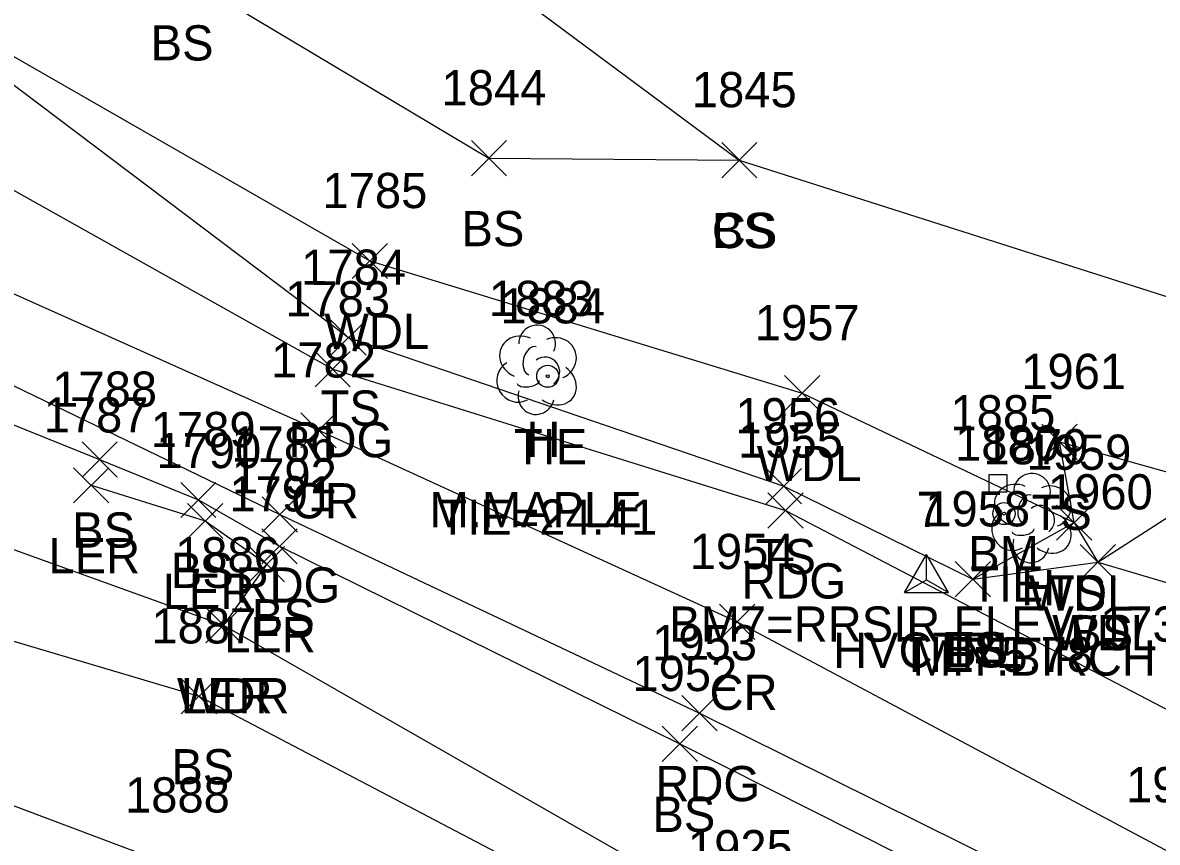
# Model space of a CAD drawing. Extents: x 1512665 to 1513714, y 110636 to 112816.
# Drawn here: x 1512769.8 to 1512834.1, y 110869.1 to 110915.7 of the extents above; entities that cross this region are included whole.
import ezdxf

# ---------------------------------------------------------------- set-up
doc = ezdxf.new("R2010")
doc.units = 0
for name, color, linetype in [('C_A', 7, 'Continuous'), ('C_C', 7, 'Continuous'), ('C_I', 7, 'Continuous'), ('CBP', 7, 'Continuous'), ('CPBM', 7, 'Continuous'), ('CPSM', 7, 'Continuous'), ('L_A', 7, 'Continuous'), ('L_C', 7, 'Continuous'), ('L_I', 7, 'Continuous'), ('L_TIC', 7, 'Continuous'), ('LARO', 7, 'Continuous'), ('LAWA', 7, 'Continuous'), ('LELB', 7, 'Continuous'), ('LTD', 7, 'Continuous'), ('P_A', 7, 'Continuous'), ('P_I', 7, 'Continuous'), ('P_TIC', 7, 'Continuous'), ('PEU', 7, 'Continuous'), ('PRC', 7, 'Continuous')]:
    doc.layers.add(name, color=color, linetype=linetype)

msp = doc.modelspace()

# ---------------------------------------------------------------- linework, layer by layer
at = {"layer": 'CBP'}
for centre, radius in [((1512799.556, 110895.606), 0.625), ((1512799.556, 110895.606), 0.0833), ((1512825.449, 110887.809), 0.625), ((1512825.449, 110887.809), 0.0833)]:
    msp.add_circle(centre, radius, dxfattribs=at)
at = {"layer": 'CPBM'}
for p, q in [((1512824.602, 110889.032), (1512824.602, 110890.032)), ((1512824.602, 110890.032), (1512825.602, 110890.032)), ((1512825.602, 110890.032), (1512825.602, 110889.032)), ((1512825.104, 110889.533), (1512825.104, 110889.533)), ((1512825.104, 110889.533), (1512825.104, 110889.533)), ((1512825.602, 110889.032), (1512824.602, 110889.032))]:
    msp.add_line(p, q, dxfattribs=at)
at = {"layer": 'CPSM'}
for p, q in [((1512819.805, 110883.327), (1512821.055, 110885.492)), ((1512819.805, 110883.327), (1512821.055, 110885.492)), ((1512819.805, 110883.327), (1512821.055, 110885.492)), ((1512819.805, 110883.327), (1512821.055, 110885.492)), ((1512819.805, 110883.327), (1512821.055, 110885.492)), ((1512819.805, 110883.327), (1512821.055, 110885.492)), ((1512819.805, 110883.327), (1512821.055, 110885.492)), ((1512822.305, 110883.327), (1512821.055, 110885.492)), ((1512821.055, 110884.048), (1512821.055, 110885.492)), ((1512822.305, 110883.327), (1512821.055, 110885.492)), ((1512821.055, 110884.048), (1512821.055, 110885.492)), ((1512822.305, 110883.327), (1512821.055, 110885.492)), ((1512821.055, 110884.048), (1512821.055, 110885.492)), ((1512822.305, 110883.327), (1512821.055, 110885.492)), ((1512821.055, 110884.048), (1512821.055, 110885.492)), ((1512822.305, 110883.327), (1512821.055, 110885.492)), ((1512821.055, 110884.048), (1512821.055, 110885.492)), ((1512822.305, 110883.327), (1512821.055, 110885.492)), ((1512821.055, 110884.048), (1512821.055, 110885.492)), ((1512822.305, 110883.327), (1512821.055, 110885.492)), ((1512821.055, 110884.048), (1512821.055, 110885.492)), ((1512819.805, 110883.327), (1512821.055, 110884.048)), ((1512819.805, 110883.327), (1512821.055, 110884.048)), ((1512819.805, 110883.327), (1512821.055, 110884.048)), ((1512819.805, 110883.327), (1512821.055, 110884.048)), ((1512819.805, 110883.327), (1512821.055, 110884.048)), ((1512819.805, 110883.327), (1512821.055, 110884.048)), ((1512819.805, 110883.327), (1512821.055, 110884.048)), ((1512821.055, 110884.048), (1512821.055, 110884.048)), ((1512821.055, 110884.048), (1512822.305, 110883.327)), ((1512821.055, 110884.048), (1512821.055, 110884.048)), ((1512821.055, 110884.048), (1512822.305, 110883.327)), ((1512821.055, 110884.048), (1512821.055, 110884.048)), ((1512821.055, 110884.048), (1512822.305, 110883.327)), ((1512821.055, 110884.048), (1512821.055, 110884.048)), ((1512821.055, 110884.048), (1512822.305, 110883.327)), ((1512821.055, 110884.048), (1512821.055, 110884.048)), ((1512821.055, 110884.048), (1512822.305, 110883.327)), ((1512821.055, 110884.048), (1512821.055, 110884.048)), ((1512821.055, 110884.048), (1512822.305, 110883.327)), ((1512821.055, 110884.048), (1512821.055, 110884.048)), ((1512821.055, 110884.048), (1512822.305, 110883.327)), ((1512819.805, 110883.327), (1512822.305, 110883.327)), ((1512819.805, 110883.327), (1512822.305, 110883.327)), ((1512819.805, 110883.327), (1512822.305, 110883.327)), ((1512819.805, 110883.327), (1512822.305, 110883.327)), ((1512819.805, 110883.327), (1512822.305, 110883.327)), ((1512819.805, 110883.327), (1512822.305, 110883.327)), ((1512819.805, 110883.327), (1512822.305, 110883.327))]:
    msp.add_line(p, q, dxfattribs=at)
at = {"layer": 'L_TIC'}
for points in [[(1512795.221, 110906.99), (1512797.221, 110908.99)], [(1512797.221, 110906.99), (1512795.221, 110908.99)], [(1512809.428, 110906.882), (1512811.428, 110908.882)], [(1512811.428, 110906.882), (1512809.428, 110908.882)], [(1512809.428, 110906.882), (1512811.428, 110908.882)], [(1512811.428, 110906.882), (1512809.428, 110908.882)], [(1512788.467, 110901.153), (1512790.467, 110903.153)], [(1512790.467, 110901.153), (1512788.467, 110903.153)], [(1512787.256, 110896.799), (1512789.256, 110898.799)], [(1512789.256, 110896.799), (1512787.256, 110898.799)], [(1512812.998, 110893.649), (1512814.998, 110895.649)], [(1512814.998, 110893.649), (1512812.998, 110895.649)], [(1512827.602, 110890.881), (1512829.602, 110892.881)], [(1512829.602, 110890.881), (1512827.602, 110892.881)], [(1512773.129, 110889.874), (1512775.129, 110891.874)], [(1512775.129, 110889.874), (1512773.129, 110891.874)], [(1512772.643, 110888.412), (1512774.643, 110890.412)], [(1512774.643, 110888.412), (1512772.643, 110890.412)], [(1512811.95, 110888.365), (1512813.95, 110890.365)], [(1512813.95, 110888.365), (1512811.95, 110890.365)], [(1512778.73, 110887.581), (1512780.73, 110889.581)], [(1512780.73, 110887.581), (1512778.73, 110889.581)], [(1512779.123, 110886.389), (1512781.123, 110888.389)], [(1512781.123, 110886.389), (1512779.123, 110888.389)], [(1512828.426, 110886.292), (1512830.426, 110888.292)], [(1512830.426, 110886.292), (1512828.426, 110888.292)], [(1512828.426, 110886.292), (1512830.426, 110888.292)], [(1512830.426, 110886.292), (1512828.426, 110888.292)], [(1512783.329, 110884.95), (1512785.329, 110886.95)], [(1512785.329, 110884.95), (1512783.329, 110886.95)], [(1512829.768, 110884.044), (1512831.768, 110886.044)], [(1512831.768, 110884.044), (1512829.768, 110886.044)], [(1512829.768, 110884.044), (1512831.768, 110886.044)], [(1512831.768, 110884.044), (1512829.768, 110886.044)], [(1512782.613, 110883.931), (1512784.613, 110885.931)], [(1512784.613, 110883.931), (1512782.613, 110885.931)], [(1512822.675, 110883.08), (1512824.675, 110885.08)], [(1512824.675, 110883.08), (1512822.675, 110885.08)], [(1512822.675, 110883.08), (1512824.675, 110885.08)], [(1512824.675, 110883.08), (1512822.675, 110885.08)], [(1512780.153, 110880.469), (1512782.153, 110882.469)], [(1512782.153, 110880.469), (1512780.153, 110882.469)], [(1512780.153, 110880.469), (1512782.153, 110882.469)], [(1512782.153, 110880.469), (1512780.153, 110882.469)], [(1512778.757, 110876.432), (1512780.757, 110878.432)], [(1512780.757, 110876.432), (1512778.757, 110878.432)], [(1512806.054, 110873.728), (1512808.054, 110875.728)], [(1512808.054, 110873.728), (1512806.054, 110875.728)]]:
    msp.add_lwpolyline(points, dxfattribs=at)
at = {"layer": 'LARO'}
msp.add_lwpolyline([(1512773.643, 110889.412), (1512780.123, 110887.389), (1512783.613, 110884.931), (1512781.153, 110881.469)], dxfattribs=at)
at = {"layer": 'LAWA'}
for points in [[(1512760.327, 110918.9), (1512789.467, 110902.153), (1512813.998, 110894.649), (1512829.426, 110887.292), (1512830.768, 110885.044), (1512838.882, 110882.648), (1512840.963, 110881.395), (1512843.663, 110878.579), (1512861.274, 110870.427), (1512887.257, 110856.133), (1512901.813, 110849.485), (1512918.081, 110842.567)], [(1512680.491, 110906.601), (1512690.439, 110907.088), (1512704.388, 110894.866), (1512725.937, 110900.333), (1512738.133, 110894.414), (1512761.21, 110888.671), (1512781.153, 110881.469), (1512810.207, 110864.835), (1512817.695, 110861.883), (1512832.481, 110853.078), (1512847.518, 110845.492), (1512864.918, 110836.029), (1512870.718, 110832.572), (1512881.895, 110825.79), (1512904.855, 110814.165), (1512921.132, 110807.474)]]:
    msp.add_lwpolyline(points, dxfattribs=at)
at = {"layer": 'LELB'}
for points in [[(1512721.894, 110948.789), (1512722.497, 110942.68), (1512730.744, 110933.358), (1512741.905, 110924.629), (1512760.327, 110918.9), (1512788.256, 110897.799), (1512812.95, 110889.365), (1512823.675, 110884.08), (1512829.426, 110887.292), (1512828.602, 110891.881), (1512837.516, 110889.389), (1512842.176, 110886.401), (1512840.963, 110881.395), (1512842.492, 110877.537), (1512859.927, 110867.233), (1512885.327, 110852.839), (1512900.342, 110845.897), (1512916.833, 110839.511), (1512931.348, 110831.636), (1512947.325, 110821.384)], [(1512700.679, 110948.394), (1512702.883, 110937.76), (1512707.699, 110928.255), (1512715.725, 110919.825), (1512729.364, 110912.396), (1512733.114, 110910.816), (1512749.564, 110901.484), (1512765.39, 110894.395), (1512774.129, 110890.874), (1512779.73, 110888.581), (1512784.329, 110885.95), (1512807.054, 110874.728), (1512832.029, 110862.151), (1512849.873, 110852.9), (1512877.541, 110837.789), (1512892.067, 110830.383), (1512907.918, 110822.224), (1512921.56, 110815.361), (1512936.611, 110807.627), (1512945.797, 110795.178), (1512949.896, 110789.739), (1512950.992, 110781.568)], [(1512775.007, 110936.434), (1512793.008, 110920.829), (1512810.428, 110907.882)], [(1512772.715, 110925.351), (1512778.581, 110918.536), (1512796.221, 110907.99), (1512810.428, 110907.882), (1512837.589, 110899.205), (1512847.527, 110891.123)], [(1512685.371, 110901.62), (1512704.388, 110894.866), (1512721.833, 110890.384), (1512736.947, 110883.291), (1512758.15, 110875.388), (1512778.26, 110867.834), (1512805.478, 110853.5), (1512829.241, 110847.859), (1512845.122, 110839.118), (1512864.918, 110836.029)], [(1512738.133, 110894.414), (1512760.682, 110883.092), (1512779.757, 110877.432), (1512809.283, 110861.943), (1512816.233, 110858.697), (1512830.12, 110852.432), (1512847.518, 110845.492)], [(1512823.675, 110884.08), (1512830.768, 110885.044), (1512837.516, 110889.389)]]:
    msp.add_lwpolyline(points, dxfattribs=at)
at = {"layer": 'LTD'}
for p, q in [((1512798.908, 110896.026), (1512798.908, 110896.026)), ((1512798.908, 110896.026), (1512798.908, 110896.026)), ((1512826.988, 110887.604), (1512826.988, 110887.604)), ((1512826.988, 110887.604), (1512826.988, 110887.604))]:
    msp.add_line(p, q, dxfattribs=at)
for centre in [(1512798.955, 110897.46), (1512827.035, 110889.038)]:
    msp.add_arc(centre, 1.047, 335.52715, 180.95627, dxfattribs=at)
for centre, major_axis, ratio, start_param, end_param in [((1512798.116, 110896.693), (1.21, -0.512), 0.895232, 1.570796, 4.712389), ((1512799.95, 110896.61), (-1.141, -0.483), 0.949671, 1.570796, 4.712389), ((1512798.7, 110896.485), (-0.208, -0.792), 0.645439, 3.141593, 6.283185), ((1512797.825, 110895.318), (0.584, -1.042), 0.959034, 3.141593, 6.283185), ((1512799.408, 110895.86), (-0.5, 0.667), 0.989748, 3.141593, 6.283185), ((1512799.908, 110895.193), (-1.09, 0.792), 0.841452, 1.570796, 4.712389), ((1512798.45, 110895.276), (-0.625, -0.083), 0.423636, 0, 3.141593), ((1512798.909, 110894.526), (0.265, 1.061), 0.942809, 1.570796, 4.712389), ((1512826.196, 110888.271), (1.21, -0.512), 0.895232, 1.570796, 4.712389), ((1512828.029, 110888.188), (-1.141, -0.483), 0.949671, 1.570796, 4.712389), ((1512826.779, 110888.062), (-0.208, -0.792), 0.645439, 3.141593, 6.283185), ((1512827.488, 110887.437), (-0.5, 0.667), 0.989748, 3.141593, 6.283185), ((1512825.905, 110886.896), (0.584, -1.042), 0.959034, 3.141593, 6.283185), ((1512827.988, 110886.771), (-1.09, 0.792), 0.841452, 1.570796, 4.712389), ((1512826.53, 110886.854), (-0.625, -0.083), 0.423636, 0, 3.141593), ((1512826.988, 110886.104), (0.265, 1.061), 0.942809, 1.570796, 4.712389)]:
    msp.add_ellipse(centre, major_axis=major_axis, ratio=ratio, start_param=start_param, end_param=end_param, dxfattribs=at)
at = {"layer": 'P_TIC'}
for points in [[(1512786.354, 110895.005), (1512788.354, 110897.005)], [(1512788.354, 110895.005), (1512786.354, 110897.005)], [(1512785.549, 110891.535), (1512787.549, 110893.535)], [(1512787.549, 110891.535), (1512785.549, 110893.535)], [(1512783.353, 110886.756), (1512785.353, 110888.756)], [(1512785.353, 110886.756), (1512783.353, 110888.756)], [(1512812.053, 110886.984), (1512814.053, 110888.984)], [(1512814.053, 110886.984), (1512812.053, 110888.984)], [(1512809.306, 110880.658), (1512811.306, 110882.658)], [(1512811.306, 110880.658), (1512809.306, 110882.658)], [(1512807.175, 110875.475), (1512809.175, 110877.475)], [(1512809.175, 110875.475), (1512807.175, 110877.475)]]:
    msp.add_lwpolyline(points, dxfattribs=at)
at = {"layer": 'PEU'}
for points in [[(1512701.918, 111049.687), (1512700.272, 111027.695), (1512701.575, 110993.777), (1512707.634, 110973.739), (1512708.973, 110956.468), (1512713.567, 110946.899), (1512719.219, 110936.541), (1512726.895, 110929.376), (1512741.614, 110919.596), (1512758.159, 110912.379), (1512787.354, 110896.005), (1512813.053, 110887.984), (1512838.367, 110874.777), (1512855.917, 110864.835), (1512882.817, 110848.349), (1512898.24, 110841.366), (1512913.486, 110833.402), (1512927.92, 110827.382), (1512944.462, 110817.212), (1512962.879, 110803.833), (1512982.126, 110789.052), (1512997.253, 110777.445), (1513011.324, 110770.561), (1513024.004, 110765.991)], [(1512687.754, 111048.122), (1512689.183, 111024.566), (1512692.043, 110992.513), (1512695.115, 110971.673), (1512700.679, 110948.394), (1512706.36, 110937.558), (1512711.027, 110929.611), (1512717.579, 110922.712), (1512730.524, 110913.856), (1512733.936, 110912.107), (1512750.227, 110902.862), (1512766.309, 110896.481), (1512784.353, 110887.756), (1512808.175, 110876.475), (1512833.242, 110864.023), (1512850.684, 110854.903), (1512878.017, 110839.243), (1512892.939, 110831.721), (1512908.545, 110823.763), (1512922.462, 110816.848)]]:
    msp.add_lwpolyline(points, dxfattribs=at)
at = {"layer": 'PRC'}
msp.add_lwpolyline([(1512693.666, 111049.349), (1512695.615, 111024.361), (1512696.792, 110993.278), (1512701.082, 110972.954), (1512704.1, 110953.937), (1512709.815, 110942.451), (1512716.007, 110931.958), (1512724.465, 110925.17), (1512739.889, 110914.845), (1512755.508, 110906.438), (1512786.549, 110892.535), (1512810.306, 110881.658), (1512835.154, 110868.413), (1512852.559, 110858.813), (1512880.606, 110843.331), (1512895.518, 110835.809), (1512910.919, 110828.697), (1512924.695, 110822.052)], dxfattribs=at)

# ---------------------------------------------------------------- texts
at = {"layer": 'C_A'}
for s, p in [('TIE', (1512797.634, 110890.606)), ('BM', (1512823.419, 110884.533)), ('TIE', (1512823.528, 110882.809)), ('HVCTRL', (1512815.748, 110879.048)), ('HVCTRL', (1512815.748, 110879.048)), ('HVCTRL', (1512815.748, 110879.048)), ('HVCTRL', (1512815.748, 110879.048)), ('HVCTRL', (1512815.748, 110879.048)), ('HVCTRL', (1512815.748, 110879.048)), ('HVCTRL', (1512815.748, 110879.048))]:
    msp.add_text(s, height=2, dxfattribs=at).set_placement(p)
at = {"layer": 'C_C'}
for s, p in [('TIE=24.41', (1512793.351, 110886.606)), ('BM7=RRSIR ELEV: 1730.00', (1512806.451, 110880.533)), ('TIE=5.78', (1512819.575, 110878.809))]:
    msp.add_text(s, height=2, dxfattribs=at).set_placement(p)
at = {"layer": 'C_I'}
for s, p in [('1884', (1512796.863, 110898.606)), ('1885', (1512822.411, 110892.533)), ('1880', (1512822.67, 110890.809)), ('7', (1512820.488, 110887.048)), ('7', (1512820.488, 110887.048)), ('7', (1512820.488, 110887.048)), ('7', (1512820.488, 110887.048)), ('7', (1512820.488, 110887.048)), ('7', (1512820.488, 110887.048)), ('7', (1512820.488, 110887.048))]:
    msp.add_text(s, height=2, dxfattribs=at).set_placement(p)
at = {"layer": 'L_A'}
for s, p in [('BS', (1512777.022, 110913.536)), ('BS', (1512794.662, 110902.99)), ('CS', (1512808.869, 110902.882)), ('BS', (1512808.869, 110902.882)), ('WDL', (1512786.884, 110897.153)), ('TS', (1512786.666, 110892.799)), ('H', (1512798.341, 110891.026)), ('WDL', (1512811.415, 110889.649)), ('TS', (1512827.012, 110886.881)), ('BS', (1512772.57, 110885.874)), ('LER', (1512771.225, 110884.412)), ('TS', (1512811.359, 110884.365)), ('BS', (1512778.171, 110883.581)), ('LER', (1512777.705, 110882.389)), ('H', (1512826.421, 110882.604)), ('WDL', (1512826.844, 110882.292)), ('TS', (1512827.836, 110882.292)), ('BS', (1512782.77, 110880.95)), ('LER', (1512781.196, 110879.931)), ('WDL', (1512828.185, 110880.044)), ('BS', (1512829.209, 110880.044)), ('TS', (1512822.084, 110879.08)), ('BS', (1512822.116, 110879.08)), ('WDR', (1512778.515, 110876.469)), ('LER', (1512778.735, 110876.469)), ('BS', (1512778.198, 110872.432)), ('BS', (1512805.495, 110869.728))]:
    msp.add_text(s, height=2, dxfattribs=at).set_placement(p)
at = {"layer": 'L_C'}
for s, p in [('M.MAPLE', (1512792.845, 110887.026)), ('M.Y.BIRCH', (1512820.248, 110878.604))]:
    msp.add_text(s, height=2, dxfattribs=at).set_placement(p)
at = {"layer": 'L_I'}
for s, p in [('1844', (1512793.529, 110910.99)), ('1845', (1512807.735, 110910.882)), ('1845', (1512807.735, 110910.882)), ('1785', (1512786.774, 110905.153)), ('1784', (1512785.563, 110900.799)), ('1883', (1512796.215, 110899.026)), ('1957', (1512811.305, 110897.649)), ('1961', (1512826.429, 110894.881)), ('1788', (1512771.436, 110893.874)), ('1787', (1512770.95, 110892.412)), ('1956', (1512810.202, 110892.365)), ('1789', (1512777.029, 110891.581)), ('1879', (1512824.287, 110890.604)), ('1790', (1512777.343, 110890.389)), ('1959', (1512826.726, 110890.292)), ('1959', (1512826.726, 110890.292)), ('1792', (1512781.636, 110888.95)), ('1791', (1512781.487, 110887.931)), ('1960', (1512827.941, 110888.044)), ('1960', (1512827.941, 110888.044)), ('1958', (1512820.982, 110887.08)), ('1958', (1512820.982, 110887.08)), ('1886', (1512778.405, 110884.469)), ('1886', (1512778.405, 110884.469)), ('1887', (1512777.064, 110880.432)), ('1952', (1512804.361, 110877.728)), ('1888', (1512775.567, 110870.834)), ('1925', (1512807.514, 110867.835))]:
    msp.add_text(s, height=2, dxfattribs=at).set_placement(p)
at = {"layer": 'P_A'}
for s, p in [('RDG', (1512784.842, 110891.005)), ('CR', (1512784.982, 110887.535)), ('RDG', (1512781.842, 110882.756)), ('RDG', (1512810.541, 110882.984)), ('CR', (1512808.739, 110876.658)), ('RDG', (1512805.663, 110871.475))]:
    msp.add_text(s, height=2, dxfattribs=at).set_placement(p)
at = {"layer": 'P_I'}
for s, p in [('1783', (1512784.661, 110899.005)), ('1782', (1512783.856, 110895.535)), ('1786', (1512781.605, 110890.756)), ('1955', (1512810.36, 110890.984)), ('1954', (1512807.613, 110884.658)), ('1953', (1512805.482, 110879.475)), ('1970', (1512832.374, 110871.413))]:
    msp.add_text(s, height=2, dxfattribs=at).set_placement(p)

doc.saveas('drawing.dxf')
